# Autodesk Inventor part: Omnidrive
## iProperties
Created: 2007-10
Part Number: Omnidrive
Document SubType Name: Modeling
Designer: lwoods
Density: 2.71 g/cm^3
Material: Aluminum-6061
Mass: 487.169 g
Surface Area: 731.322 cm^2
Volume: 179.767 cm^3
Author: lwoods
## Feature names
1. Extrusion1
2. Extrusion2
3. Circular Pattern1
4. Extrusion3
5. Circular Pattern2
6. Fillet1
7. Extrusion4
8. Extrusion5
9. Extrusion6
10. Extrusion7
11. Circular Pattern3
12. Extrusion8
13. Extrusion9
14. Circular Pattern4
15. Fillet2
16. Fillet3
17. Fillet4
18. Fillet8
19. Fillet9
20. Extrusion11
21. Circular Pattern6
22. Extrusion12
23. Circular Pattern7
24. Extrusion10
25. Circular Pattern5
26. Fillet16
27. Extrusion15
28. Fillet17
29. Circular Pattern9
30. Extrusion16
31. Extrusion17
32. Circular Pattern10
33. Extrusion18
34. Extrusion19
35. Circular Pattern11
36. Fillet18
37. Fillet21
38. Extrusion21
39. Circular Pattern12
